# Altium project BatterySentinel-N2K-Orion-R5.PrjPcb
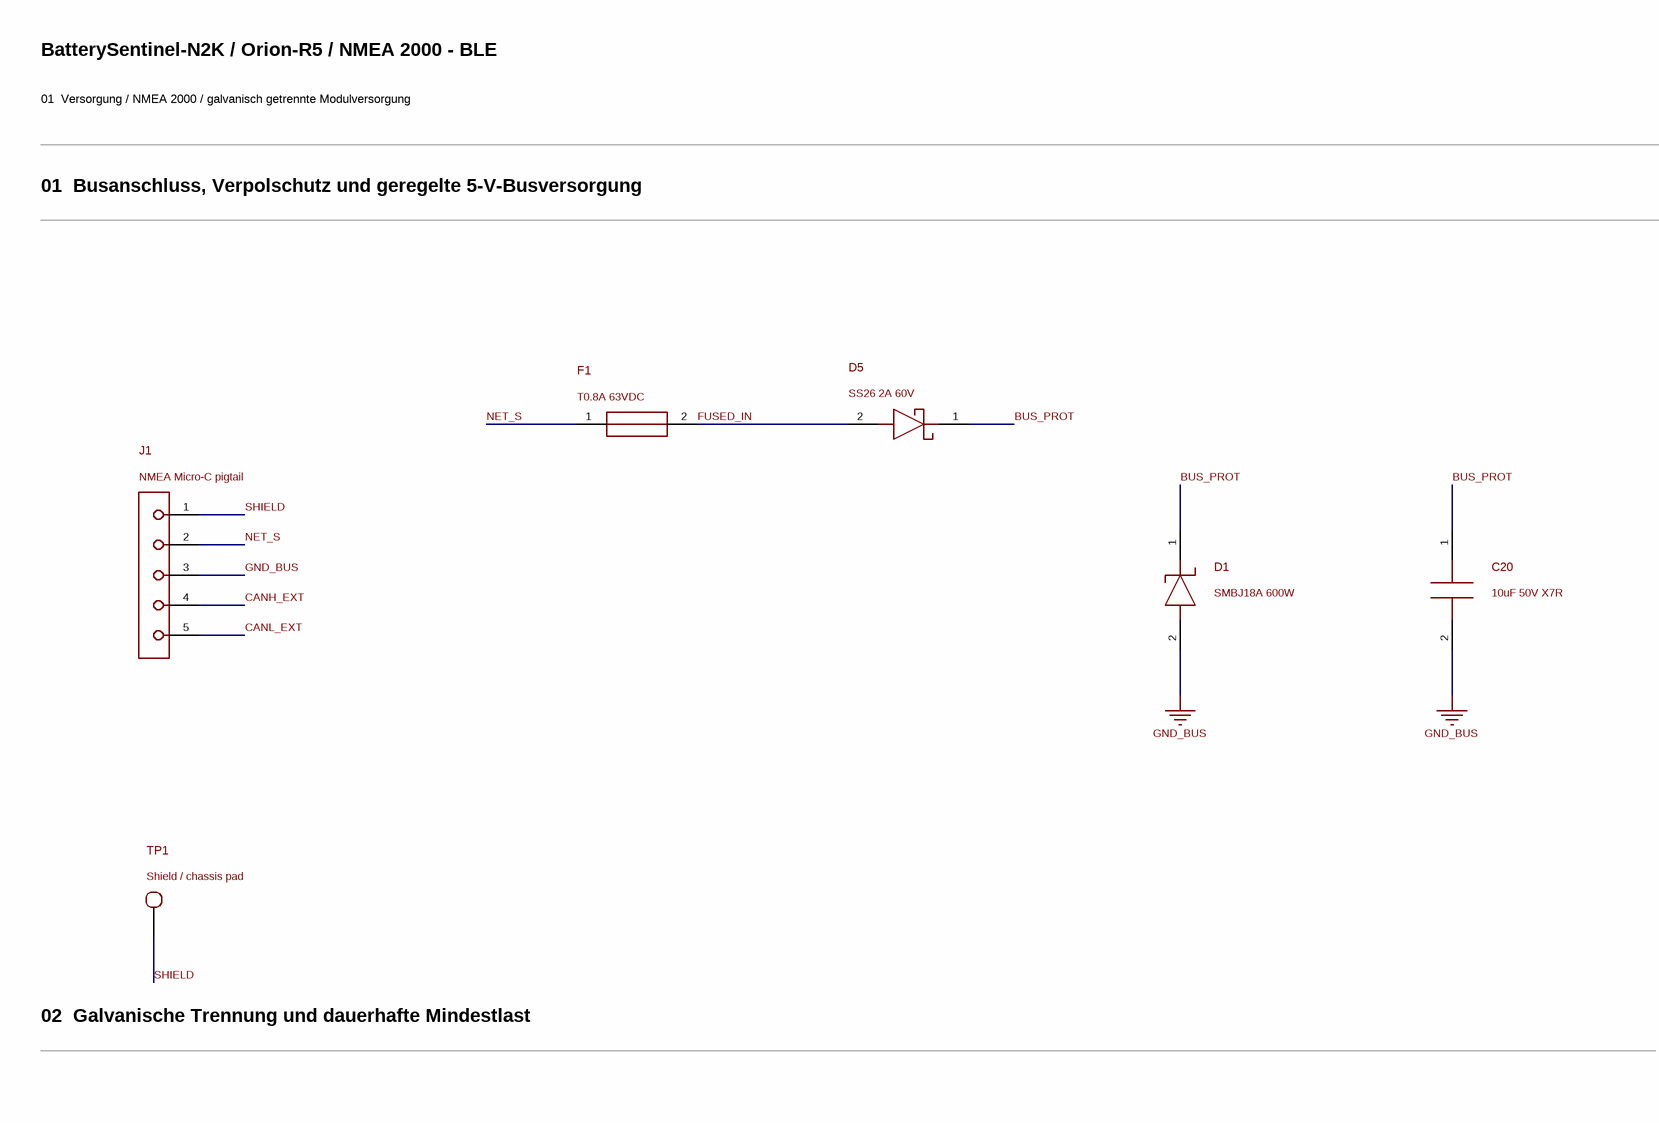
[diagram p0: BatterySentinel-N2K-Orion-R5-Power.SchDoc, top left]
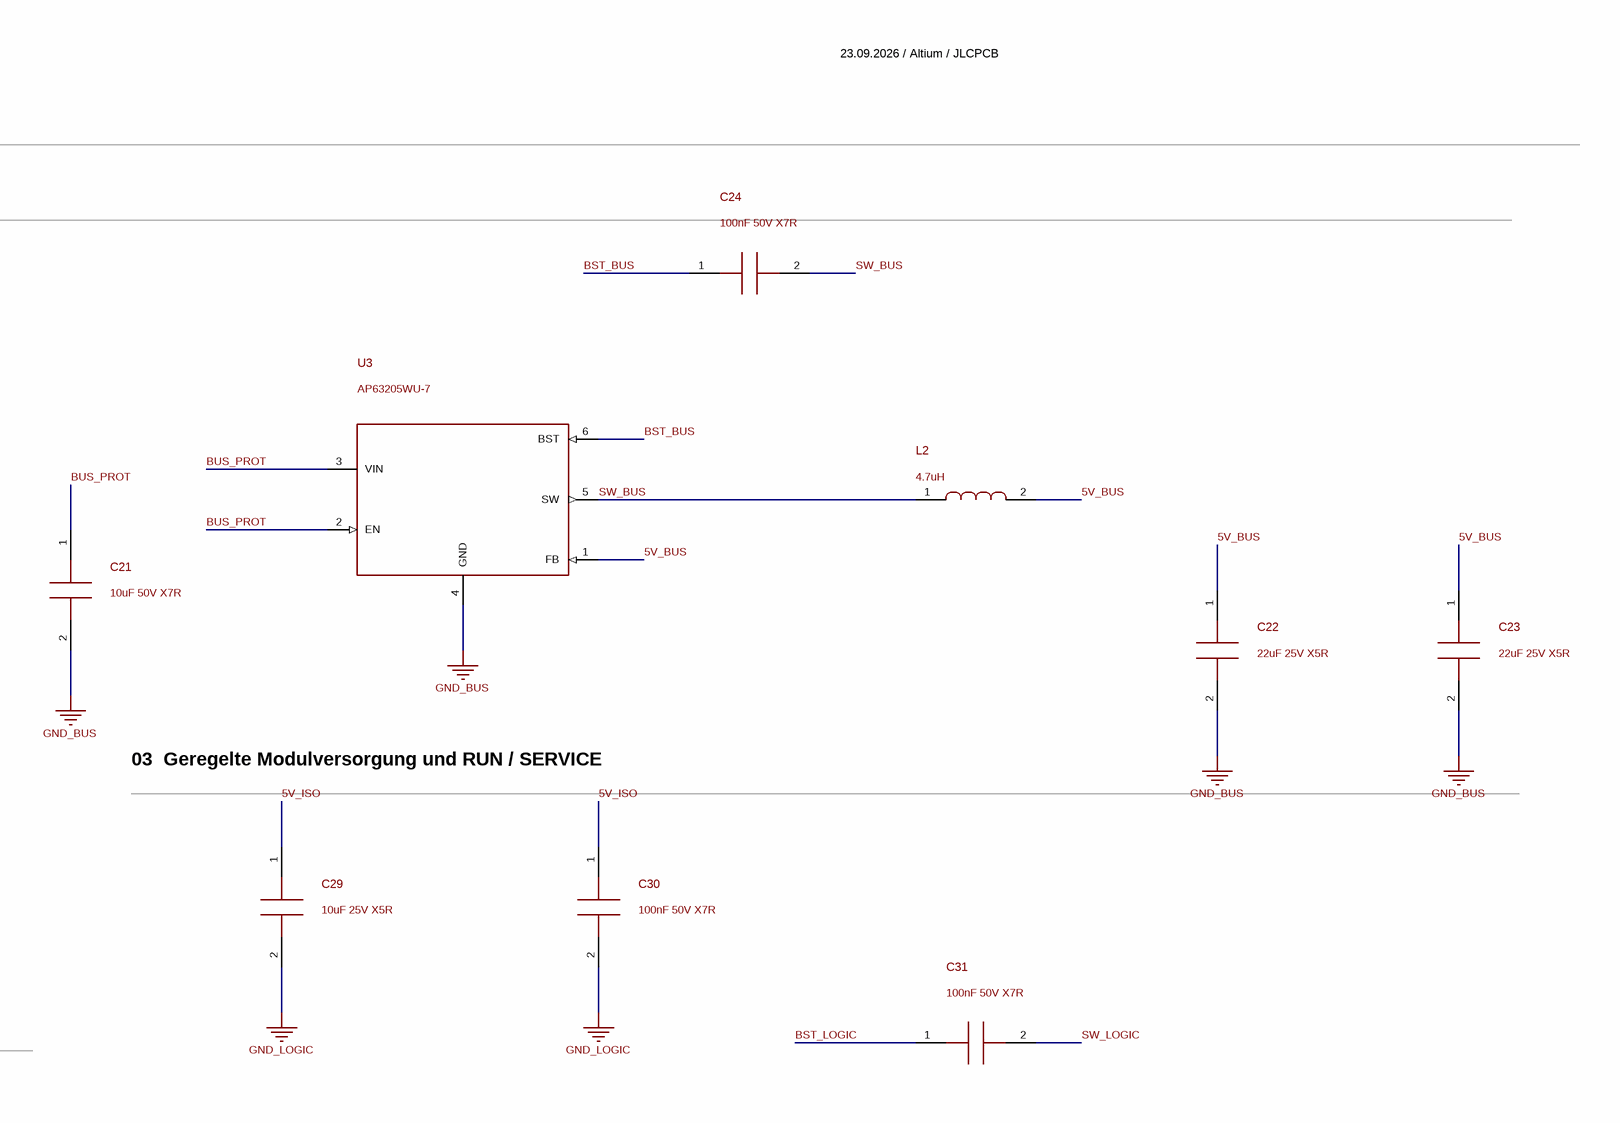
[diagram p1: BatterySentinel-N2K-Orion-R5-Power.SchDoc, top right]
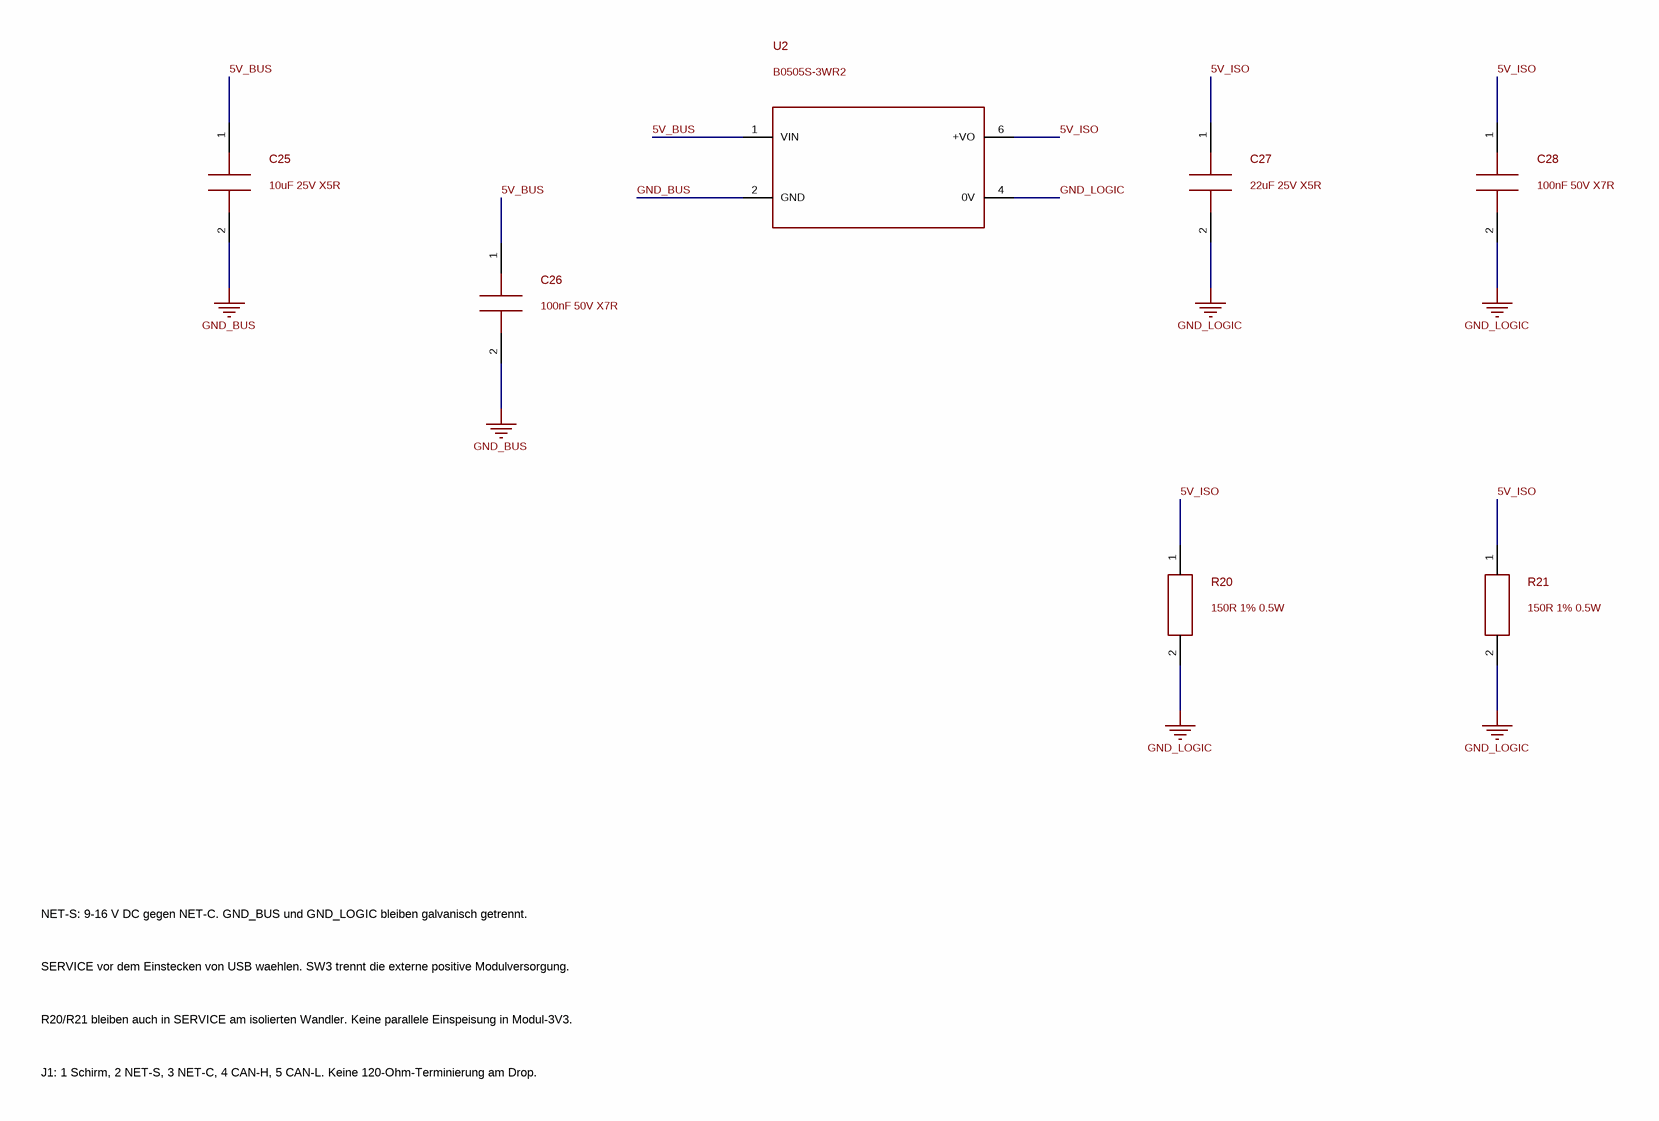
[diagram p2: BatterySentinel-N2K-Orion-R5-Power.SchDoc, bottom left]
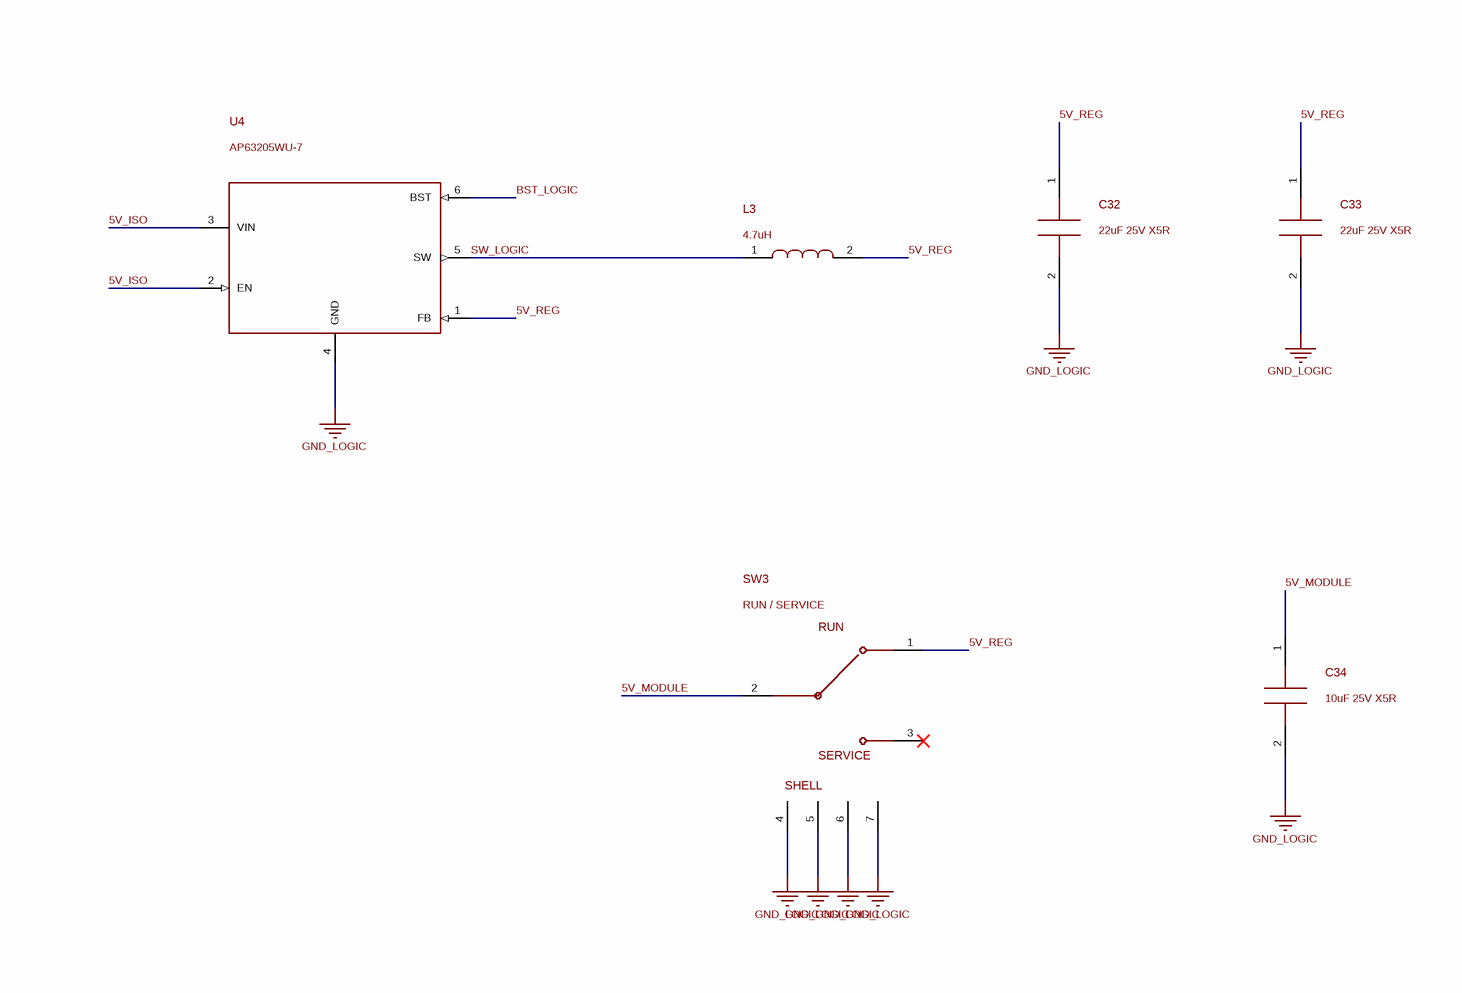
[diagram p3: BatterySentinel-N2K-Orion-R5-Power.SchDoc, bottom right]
2 sheets, 37 parts. Net scope: global (net labels, ports and power ports of the same name join across sheets).
Board file: BatterySentinel-N2K-Orion-R5.PcbDoc
Sheets:
  BatterySentinel-N2K-Orion-R5-Power.SchDoc
  BatterySentinel-N2K-Orion-R5-Logic.SchDoc

## Sheet BatterySentinel-N2K-Orion-R5-Power.SchDoc
size A2

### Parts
C20  10uF 50V X7R  [C1210]
C21  10uF 50V X7R  [C1210]
C22  22uF 25V X5R  [C1206]
C23  22uF 25V X5R  [C1206]
C24  100nF 50V X7R  [C0603]
C25  10uF 25V X5R  [C0805]
C26  100nF 50V X7R  [C0603]
C27  22uF 25V X5R  [C1206]
C28  100nF 50V X7R  [C0603]
C29  10uF 25V X5R  [C0805]
C30  100nF 50V X7R  [C0603]
C31  100nF 50V X7R  [C0603]
C32  22uF 25V X5R  [C1206]
C33  22uF 25V X5R  [C1206]
C34  10uF 25V X5R  [C0805]
D1  SMBJ18A 600W  [SMB]
D5  SS26 2A 60V  [SMA]
F1  T0.8A 63VDC  [BOURNS_SF1206S]
J1  NMEA Micro-C pigtail  [PIGTAIL_5_P3_D1P3]
L2  4.7uH  [SUNLORD_SWPA4030]
L3  4.7uH  [SUNLORD_SWPA4030]
R20  150R 1% 0.5W  [R1206]
R21  150R 1% 0.5W  [R1206]
SW3  RUN / SERVICE  [GSWITCH_MK12C02_G020]
TP1  Shield / chassis pad  [TESTPOINT_2MM]
U2  B0505S-3WR2  [EVISUN_B0505S_3WR2]
U3  AP63205WU-7  [TSOT26_DIODES]
U4  AP63205WU-7  [TSOT26_DIODES]

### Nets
GND_BUS: C20.2 C21.2 C22.2 C23.2 C25.2 C26.2 D1.2(A) J1.3(NET-C) U2.2(GND) U3.4(GND)
GND_LOGIC: C27.2 C28.2 C29.2 C30.2 C32.2 C33.2 C34.2 R20.2 R21.2 SW3.4(SHIELD1) SW3.5(SHIELD2) SW3.6(SHIELD3) SW3.7(SHIELD4) U2.4(0V) U4.4(GND)
5V_BUS: C22.1 C23.1 C25.1 C26.1 L2.2 U2.1(VIN) U3.1(FB)
5V_ISO: C27.1 C28.1 C29.1 C30.1 R20.1 R21.1 U2.6(+VO) U4.2(EN) U4.3(VIN)
5V_MODULE: C34.1 SW3.2(COMMON)
5V_REG: C32.1 C33.1 L3.2 SW3.1(RUN_IN) U4.1(FB)
BST_BUS: C24.1 U3.6(BST)
BST_LOGIC: C31.1 U4.6(BST)
BUS_PROT: C20.1 C21.1 D1.1(K) D5.1(K) U3.2(EN) U3.3(VIN)
CANH_EXT: J1.4(CAN-H)
CANL_EXT: J1.5(CAN-L)
FUSED_IN: D5.2(A) F1.2
NET_S: F1.1 J1.2(NET-S)
SHIELD: J1.1(SHIELD) TP1.1(SHIELD)
SW_BUS: C24.2 L2.1 U3.5(SW)
SW_LOGIC: C31.2 L3.1 U4.5(SW)

Not connected (* = marked no-connect by the designer): SW3 3(SERVICE_NC)*

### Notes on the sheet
- BatterySentinel-N2K / Orion-R5 / NMEA 2000 - BLE
- 23.09.2026 / Altium / JLCPCB
- 01  Versorgung / NMEA 2000 / galvanisch getrennte Modulversorgung
- 01  Busanschluss, Verpolschutz und geregelte 5-V-Busversorgung
- 03  Geregelte Modulversorgung und RUN / SERVICE
- 02  Galvanische Trennung und dauerhafte Mindestlast
- NET-S: 9-16 V DC gegen NET-C. GND_BUS und GND_LOGIC bleiben galvanisch getrennt.
- SERVICE vor dem Einstecken von USB waehlen. SW3 trennt die externe positive Modulversorgung.
- R20/R21 bleiben auch in SERVICE am isolierten Wandler. Keine parallele Einspeisung in Modul-3V3.
- J1: 1 Schirm, 2 NET-S, 3 NET-C, 4 CAN-H, 5 CAN-L. Keine 120-Ohm-Terminierung am Drop.

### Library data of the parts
C20 = R5_C20_10uF: Manufacturer: Samsung Electro-Mechanics; MPN: CL32B106KBJNNNE; ReviewStatus: R5 placement with enclosure interface
C21 = R5_C21_10uF: Manufacturer: Samsung Electro-Mechanics; MPN: CL32B106KBJNNNE; ReviewStatus: R5 placement with enclosure interface
C22 = R5_C22_22uF: Manufacturer: Samsung Electro-Mechanics; MPN: CL31A226KAHNNNE; ReviewStatus: R5 placement with enclosure interface
C23 = R5_C23_22uF: Manufacturer: Samsung Electro-Mechanics; MPN: CL31A226KAHNNNE; ReviewStatus: R5 placement with enclosure interface
C24 = R5_C24_100nF: Manufacturer: YAGEO; MPN: CC0603KRX7R9BB104; ReviewStatus: R5 placement with enclosure interface
C25 = R5_C25_10uF: Manufacturer: Samsung Electro-Mechanics; MPN: CL21A106KAYNNNE; ReviewStatus: R5 placement with enclosure interface
C26 = R5_C26_100nF: Manufacturer: YAGEO; MPN: CC0603KRX7R9BB104; ReviewStatus: R5 placement with enclosure interface
C27 = R5_C27_22uF: Manufacturer: Samsung Electro-Mechanics; MPN: CL31A226KAHNNNE; ReviewStatus: R5 placement with enclosure interface
C28 = R5_C28_100nF: Manufacturer: YAGEO; MPN: CC0603KRX7R9BB104; ReviewStatus: R5 placement with enclosure interface
C29 = R5_C29_10uF: Manufacturer: Samsung Electro-Mechanics; MPN: CL21A106KAYNNNE; ReviewStatus: R5 placement with enclosure interface
C30 = R5_C30_100nF: Manufacturer: YAGEO; MPN: CC0603KRX7R9BB104; ReviewStatus: R5 placement with enclosure interface
C31 = R5_C31_100nF: Manufacturer: YAGEO; MPN: CC0603KRX7R9BB104; ReviewStatus: R5 placement with enclosure interface
C32 = R5_C32_22uF: Manufacturer: Samsung Electro-Mechanics; MPN: CL31A226KAHNNNE; ReviewStatus: R5 placement with enclosure interface
C33 = R5_C33_22uF: Manufacturer: Samsung Electro-Mechanics; MPN: CL31A226KAHNNNE; ReviewStatus: R5 placement with enclosure interface
C34 = R5_C34_10uF: 10uF local module5V reservoir after RUN/SERVICE switch; Manufacturer: Samsung Electro-Mechanics; MPN: CL21A106KAYNNNE; ReviewStatus: R5 placement with enclosure interface
D1 = R5_D1_SMBJ18A: Manufacturer: BORN; ReviewStatus: R5 placement with enclosure interface
D5 = R5_D5_SS26: Manufacturer: MDD(Microdiode Semiconductor); ReviewStatus: R5 placement with enclosure interface
F1 = R5_F1_T0.8A: 0.8 A slow-blow SMD ceramic fuse, 63 VDC, 50 A interrupt rating; Manufacturer: BOURNS; MPN: SF-1206S080-2; ReviewStatus: R5 placement with enclosure interface
J1 = R5_J1_NMEA: Five direct wire-solder pads for a separately selected Micro-C cable; this is a PCB interface, not an invented connector MPN or face view; ReviewStatus: R5 placement with enclosure interface
L2 = R5_L2_4.7uH: Manufacturer: Sunlord; MPN: SWPA4030S4R7MT; ReviewStatus: R5 placement with enclosure interface
L3 = R5_L3_4.7uH: Manufacturer: Sunlord; MPN: SWPA4030S4R7MT; ReviewStatus: R5 placement with enclosure interface
R20 = R5_R20_150R: Manufacturer: SEI(Stackpole Elec); MPN: RNCP1206FTD150R; ReviewStatus: R5 placement with enclosure interface
R21 = R5_R21_150R: Manufacturer: SEI(Stackpole Elec); MPN: RNCP1206FTD150R; ReviewStatus: R5 placement with enclosure interface
SW3 = R5_SW3_RUN: Side-actuated SPDT service supply disconnect, 1A at6V, original SuperMini USB service; Manufacturer: G-Switch; MPN: MK-12C02-G020; ReviewStatus: R5 placement with enclosure interface
TP1 = R5_TP1_Shield: Shield / chassis pad - generic specification; manufacturer/MPN not selected; ReviewStatus: R5 placement with enclosure interface
U2 = R5_U2_B0505S_3WR2: Manufacturer: EVISUN; ReviewStatus: R5 placement with enclosure interface
U3 = R5_U3_AP63205WU_7: Manufacturer: Diodes Incorporated; ReviewStatus: R5 placement with enclosure interface
U4 = R5_U4_AP63205WU_7: Isolated-side 5V buck / high-duty pass-through, feeding physical RUN/SERVICE disconnect; Manufacturer: Diodes Incorporated; ReviewStatus: R5 placement with enclosure interface

## Sheet BatterySentinel-N2K-Orion-R5-Logic.SchDoc
size A2
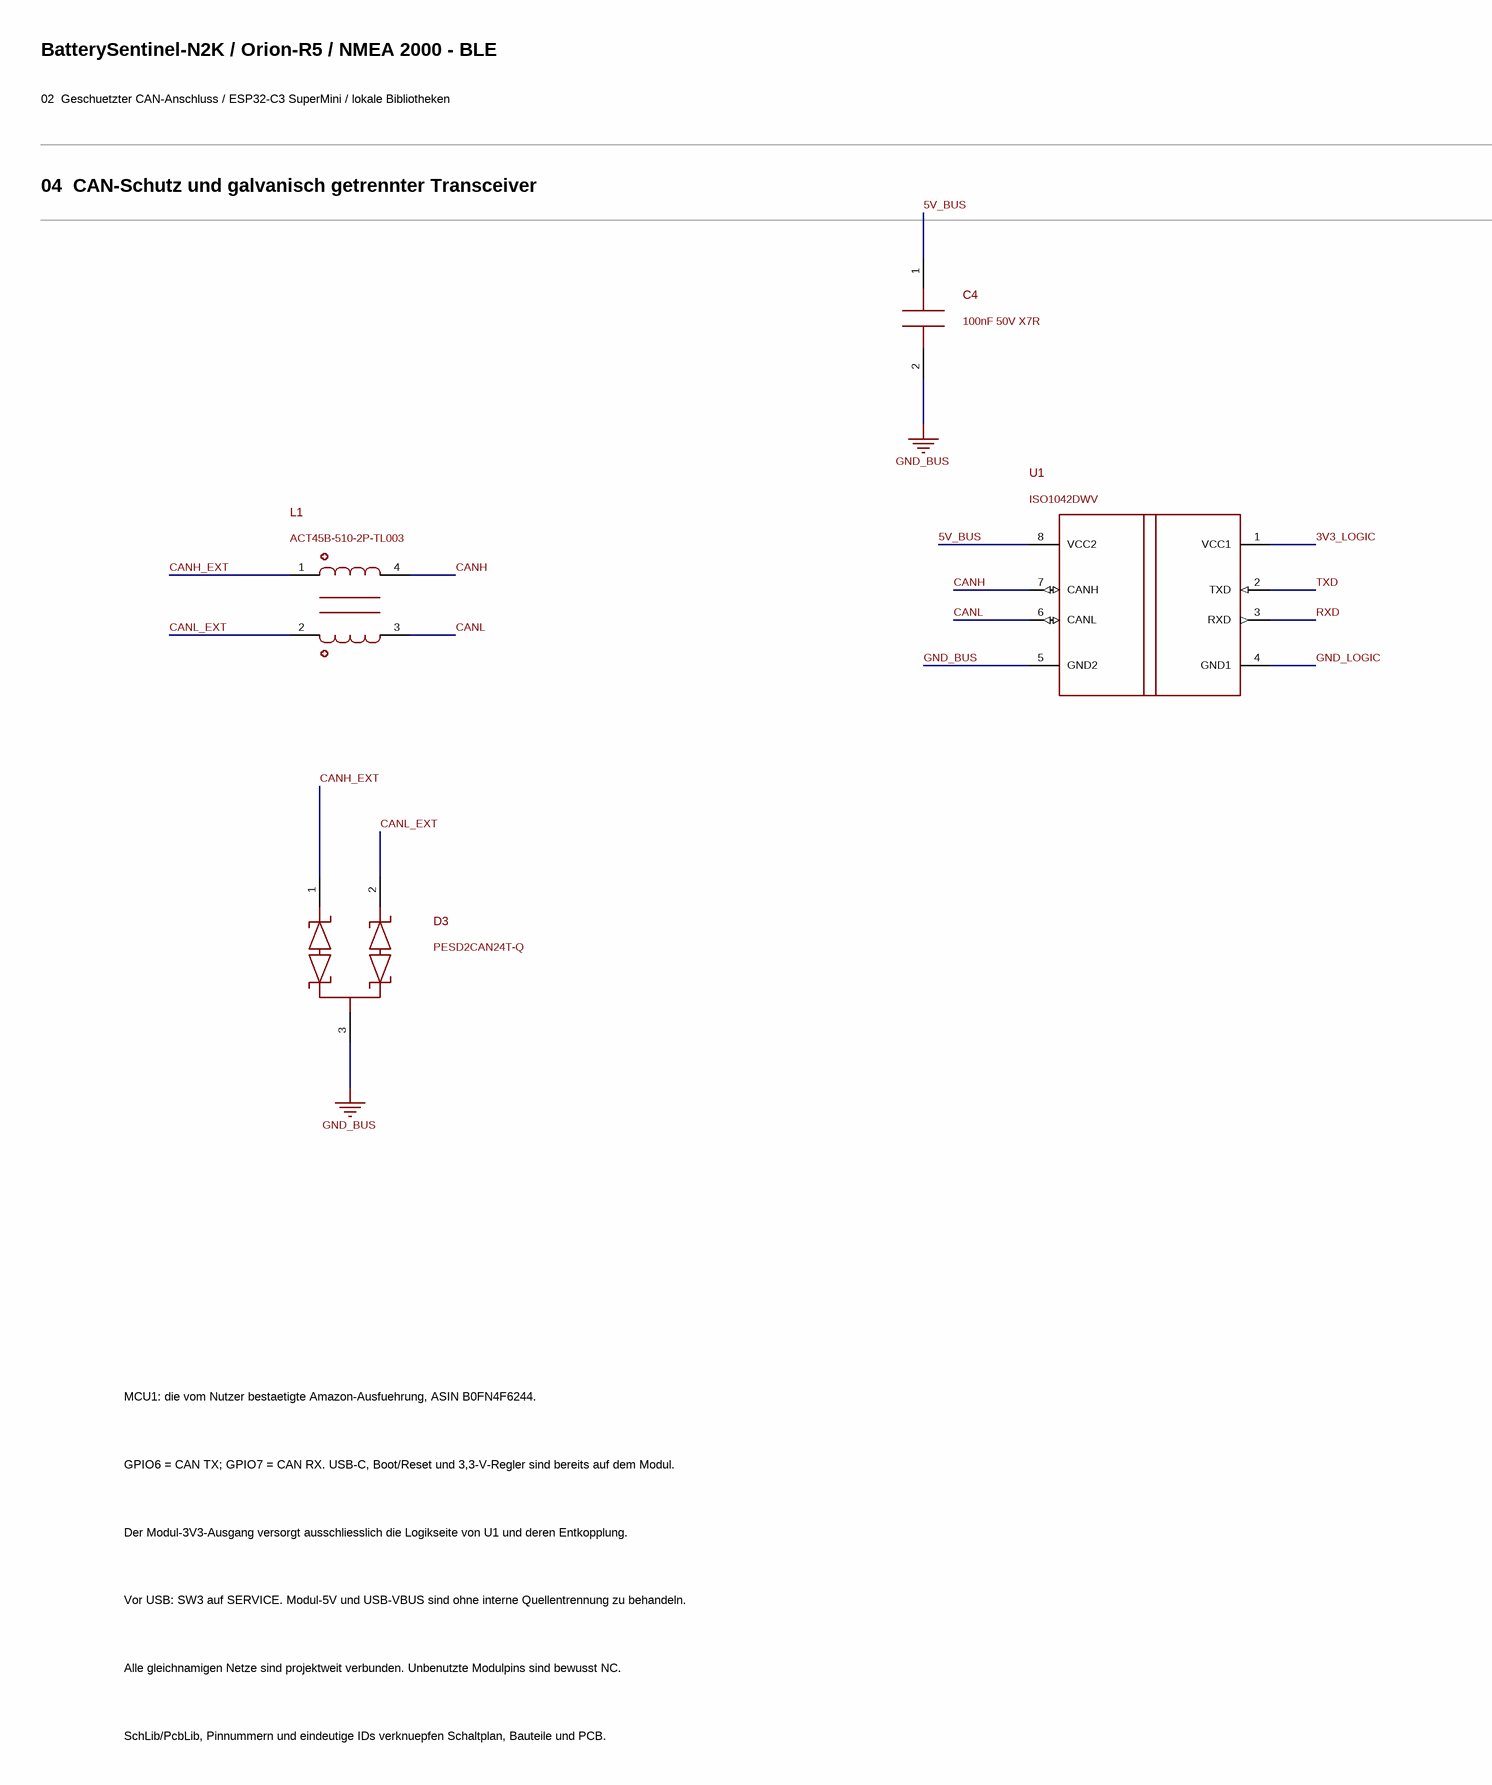
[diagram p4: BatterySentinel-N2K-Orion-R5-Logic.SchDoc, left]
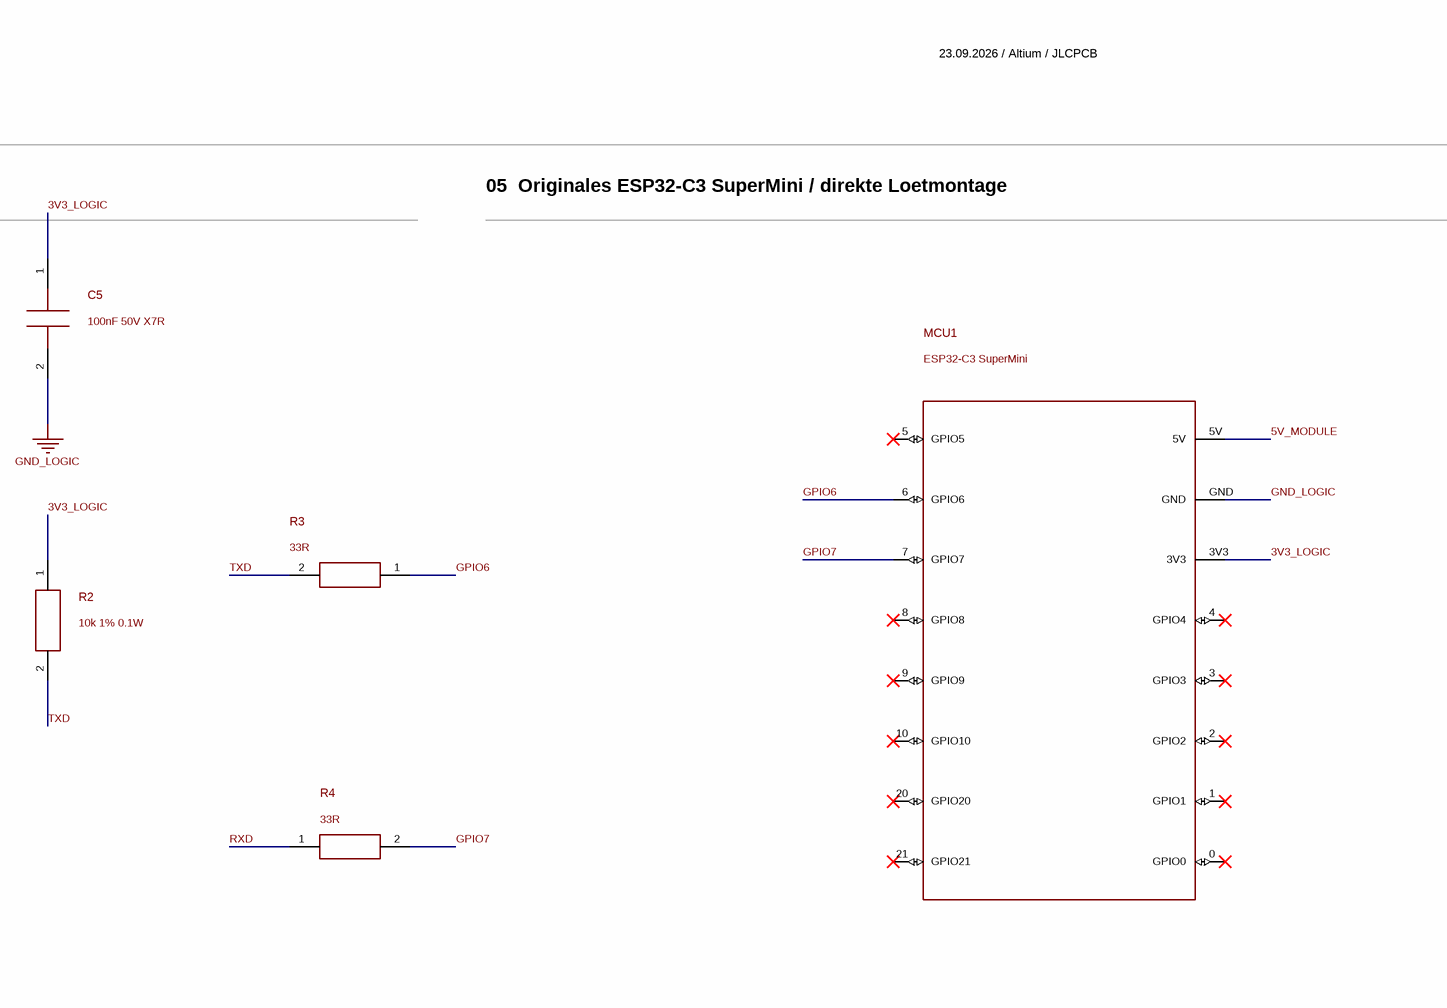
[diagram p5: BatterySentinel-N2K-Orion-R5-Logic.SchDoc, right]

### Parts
C4  100nF 50V X7R  [C0603]
C5  100nF 50V X7R  [C0603]
D3  PESD2CAN24T-Q  [SOT23_NEXPERIA_REFLOW]
L1  ACT45B-510-2P-TL003  [ACT45B]
MCU1  ESP32-C3 SuperMini  [SUPERC3_B0FN4F6244_CAST16_SMD]
R2  10k 1% 0.1W  [R0603]
R3  33R  [R0603]
R4  33R  [R0603]
U1  ISO1042DWV  [SOIC8_DWV]

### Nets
GND_BUS: C4.2 D3.3(CC) U1.5(GND2)
GND_LOGIC: C5.2 MCU1.GND U1.4(GND1)
3V3_LOGIC: C5.1 MCU1.3V3 R2.1 U1.1(VCC1)
5V_BUS: C4.1 U1.8(VCC2)
5V_MODULE: MCU1.5V
CANH: L1.4(H_IC) U1.7(CANH)
CANH_EXT: D3.1(K1) L1.1(H_EXT)
CANL: L1.3(L_IC) U1.6(CANL)
CANL_EXT: D3.2(K2) L1.2(L_EXT)
GPIO6: MCU1.6(GPIO6) R3.1
GPIO7: MCU1.7(GPIO7) R4.2
RXD: R4.1 U1.3(RXD)
TXD: R2.2 R3.2 U1.2(TXD)

Not connected (* = marked no-connect by the designer): MCU1 0(GPIO0)* 1(GPIO1)* 2(GPIO2)* 3(GPIO3)* 4(GPIO4)* 5(GPIO5)* 8(GPIO8)* 9(GPIO9)* 10(GPIO10)* 20(GPIO20)* 21(GPIO21)*

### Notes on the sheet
- BatterySentinel-N2K / Orion-R5 / NMEA 2000 - BLE
- 23.09.2026 / Altium / JLCPCB
- 02  Geschuetzter CAN-Anschluss / ESP32-C3 SuperMini / lokale Bibliotheken
- 04  CAN-Schutz und galvanisch getrennter Transceiver
- 05  Originales ESP32-C3 SuperMini / direkte Loetmontage
- MCU1: die vom Nutzer bestaetigte Amazon-Ausfuehrung, ASIN B0FN4F6244.
- GPIO6 = CAN TX; GPIO7 = CAN RX. USB-C, Boot/Reset und 3,3-V-Regler sind bereits auf dem Modul.
- Der Modul-3V3-Ausgang versorgt ausschliesslich die Logikseite von U1 und deren Entkopplung.
- Vor USB: SW3 auf SERVICE. Modul-5V und USB-VBUS sind ohne interne Quellentrennung zu behandeln.
- Alle gleichnamigen Netze sind projektweit verbunden. Unbenutzte Modulpins sind bewusst NC.
- SchLib/PcbLib, Pinnummern und eindeutige IDs verknuepfen Schaltplan, Bauteile und PCB.

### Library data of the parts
C4 = R5_C4_100nF: 100nF 16V X7R - generic specification; manufacturer/MPN not selected; Manufacturer: YAGEO; MPN: CC0603KRX7R9BB104; ReviewStatus: R5 placement with enclosure interface
C5 = R5_C5_100nF: 100nF 16V X7R - generic specification; manufacturer/MPN not selected; Manufacturer: YAGEO; MPN: CC0603KRX7R9BB104; ReviewStatus: R5 placement with enclosure interface
D3 = R5_D3_PESD2CAN24T_Q: Manufacturer: Nexperia; MPN: PESD2CAN24T-QR; ReviewStatus: R5 placement with enclosure interface
L1 = R5_L1_ACT45B_510_2P_TL003: Manufacturer: TDK; ReviewStatus: R5 placement with enclosure interface
MCU1 = R5_MCU1_ESP32_C3: User-selected C3 SuperMini; original onboard USB/BOOT/RESET; direct castellated solder mounting; Manufacturer: Meshnology (seller brand; OEM undisclosed); MPN: ESP32-C3 SuperMini / ASIN B0FN4F6244; ReviewStatus: R5 placement with enclosure interface
R2 = R5_R2_10k: 10k - generic specification; manufacturer/MPN not selected; Manufacturer: UNI-ROYAL(Uniroyal Elec); MPN: 0603WAF1002T5E; ReviewStatus: R5 placement with enclosure interface
R3 = R5_R3_33R: 33R - generic specification; manufacturer/MPN not selected; Manufacturer: UNI-ROYAL(Uniroyal Elec); MPN: 0603WAF330JT5E; Role: R_TX; ReviewStatus: R5 placement with enclosure interface
R4 = R5_R4_33R: 33R - generic specification; manufacturer/MPN not selected; Manufacturer: UNI-ROYAL(Uniroyal Elec); MPN: 0603WAF330JT5E; Role: R_RX; ReviewStatus: R5 placement with enclosure interface
U1 = R5_U1_ISO1042DWV: Manufacturer: Texas Instruments; MPN: ISO1042DWVR; ReviewStatus: R5 placement with enclosure interface

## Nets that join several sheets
GND_BUS: BatterySentinel-N2K-Orion-R5-Power (10 pins), BatterySentinel-N2K-Orion-R5-Logic (C4.2 D3.3 U1.5)
GND_LOGIC: BatterySentinel-N2K-Orion-R5-Power (15 pins), BatterySentinel-N2K-Orion-R5-Logic (C5.2 MCU1.GND U1.4)
5V_BUS: BatterySentinel-N2K-Orion-R5-Power (7 pins), BatterySentinel-N2K-Orion-R5-Logic (C4.1 U1.8)
5V_MODULE: BatterySentinel-N2K-Orion-R5-Power (C34.1 SW3.2), BatterySentinel-N2K-Orion-R5-Logic (MCU1.5V)
CANH_EXT: BatterySentinel-N2K-Orion-R5-Power (J1.4), BatterySentinel-N2K-Orion-R5-Logic (D3.1 L1.1)
CANL_EXT: BatterySentinel-N2K-Orion-R5-Power (J1.5), BatterySentinel-N2K-Orion-R5-Logic (D3.2 L1.2)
